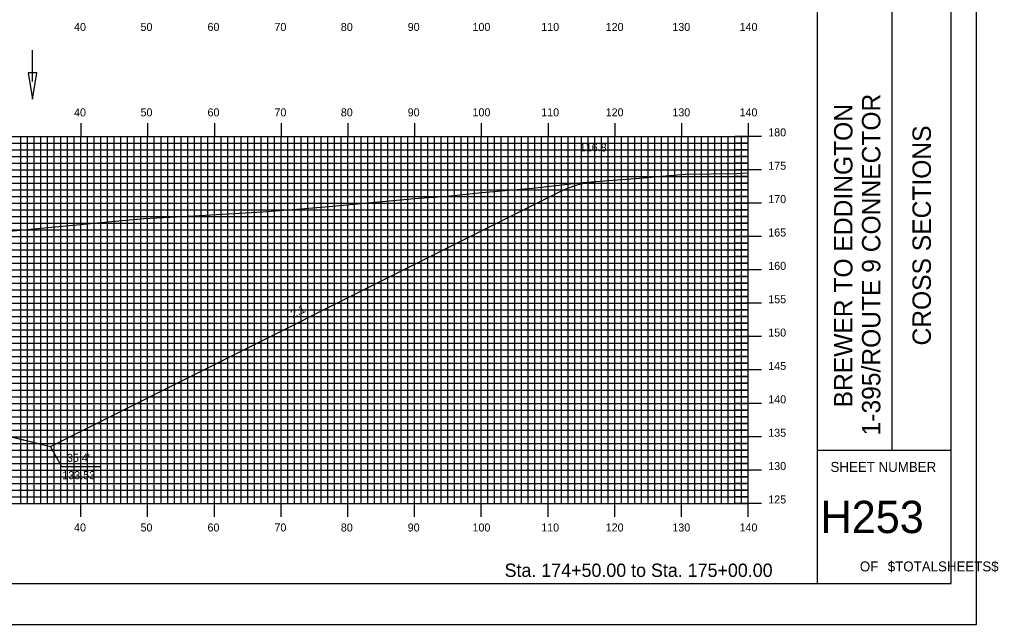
# Model space of a CAD drawing. Extents: x 1783828 to 1784171, y 442591 to 442811.
# Drawn here: x 1784024.3 to 1784171, y 442590.5 to 442681.2 of the extents above; entities that cross this region are included whole.
import ezdxf

# ---------------------------------------------------------------- set-up
doc = ezdxf.new("R2010")
doc.units = 0
for name, color, linetype in [('ANNOTATION', 7, 'Continuous'), ('BORDER', 7, 'Continuous'), ('D_Drainage_Ditch_Line', 7, 'Continuous'), ('D_Roadway_Centerline', 7, 'Continuous'), ('D_Roadway_SlopeLines', 7, 'Continuous'), ('D_Text_Standard', 7, 'Continuous'), ('H_V ANNOTATION', 7, 'Continuous'), ('MAJOR', 7, 'Continuous'), ('MINOR', 7, 'Continuous'), ('PLOT BOUNDARY', 7, 'Continuous'), ('S_Roadway_Centerline', 7, 'Continuous')]:
    doc.layers.add(name, color=color, linetype=linetype)

msp = doc.modelspace()

# ---------------------------------------------------------------- linework, layer by layer
at = {"layer": 'ANNOTATION'}
msp.add_lwpolyline([(1784036.34, 442614.18), (1784030.65, 442614.18), (1784028.93, 442617.2)], dxfattribs=at)
at = {"layer": 'BORDER'}
for p, q in [((1784143.89, 442596.67), (1784143.89, 442806.67)), ((1784155.07, 442616.67), (1784155.07, 442686.67)), ((1784155.07, 442616.67), (1784155.07, 442686.67)), ((1784143.89, 442616.67), (1784163.89, 442616.67)), ((1784143.89, 442616.67), (1784163.89, 442616.67))]:
    msp.add_line(p, q, dxfattribs=at)
msp.add_lwpolyline([(1783843.89, 442596.67), (1784163.89, 442596.67), (1784163.89, 442806.67), (1783843.89, 442806.67)], close=True, dxfattribs=at)
at = {"layer": 'D_Drainage_Ditch_Line'}
msp.add_line((1784026.24, 442671.87), (1784026.24, 442676.57), dxfattribs=at)
msp.add_lwpolyline([(1784026.89, 442673.18), (1784025.58, 442673.18), (1784026.24, 442669.24)], close=True, dxfattribs=at)
at = {"layer": 'D_Roadway_Centerline'}
msp.add_lwpolyline([(1783909.48, 442640.49), (1783910.73, 442640.48), (1783911.98, 442640.3), (1783913.23, 442639.94), (1783914.48, 442639.4), (1783959.31, 442616.98), (1783963.31, 442617.98), (1783973.49, 442620.53), (1783981.49, 442620.85), (1783993.49, 442621.11), (1784005.49, 442621.38), (1784013.49, 442621.06), (1784023.66, 442618.51), (1784028.93, 442617.2), (1784105.33, 442655.4), (1784106.58, 442655.96), (1784107.83, 442656.39), (1784109.08, 442656.7), (1784110.33, 442656.87)], dxfattribs=at)
at = {"layer": 'D_Roadway_SlopeLines'}
for points in [[(1784028.93, 442617.2), (1784105.33, 442655.4), (1784106.58, 442655.96), (1784107.83, 442656.39), (1784109.08, 442656.7), (1784110.33, 442656.87)], [(1784013.49, 442621.06), (1784028.93, 442617.2)]]:
    msp.add_lwpolyline(points, dxfattribs=at)
at = {"layer": 'MAJOR'}
for p, q in [((1784033.49, 442665.67), (1784033.49, 442663.67)), ((1784043.49, 442665.67), (1784043.49, 442663.67)), ((1784053.49, 442665.67), (1784053.49, 442663.67)), ((1784063.49, 442665.67), (1784063.49, 442663.67)), ((1784073.49, 442665.67), (1784073.49, 442663.67)), ((1784083.49, 442665.67), (1784083.49, 442663.67)), ((1784093.49, 442665.67), (1784093.49, 442663.67)), ((1784103.49, 442665.67), (1784103.49, 442663.67)), ((1784113.49, 442665.67), (1784113.49, 442663.67)), ((1784123.49, 442665.67), (1784123.49, 442663.67)), ((1784133.49, 442665.67), (1784133.49, 442663.67)), ((1783853.49, 442663.67), (1784133.49, 442663.67)), ((1783853.49, 442663.67), (1784133.49, 442663.67)), ((1784033.49, 442608.67), (1784033.49, 442663.67)), ((1784043.49, 442608.67), (1784043.49, 442663.67)), ((1784053.49, 442608.67), (1784053.49, 442663.67)), ((1784063.49, 442608.67), (1784063.49, 442663.67)), ((1784073.49, 442608.67), (1784073.49, 442663.67)), ((1784083.49, 442608.67), (1784083.49, 442663.67)), ((1784093.49, 442608.67), (1784093.49, 442663.67)), ((1784103.49, 442608.67), (1784103.49, 442663.67)), ((1784113.49, 442608.67), (1784113.49, 442663.67)), ((1784123.49, 442608.67), (1784123.49, 442663.67)), ((1784135.49, 442663.67), (1784131.48, 442663.67)), ((1784133.49, 442608.67), (1784133.49, 442663.67)), ((1784133.49, 442608.67), (1784133.49, 442663.67)), ((1783853.49, 442658.67), (1784133.49, 442658.67)), ((1784135.49, 442658.67), (1784131.48, 442658.67)), ((1783853.49, 442653.67), (1784133.49, 442653.67)), ((1784135.49, 442653.67), (1784131.48, 442653.67)), ((1783853.49, 442648.67), (1784133.49, 442648.67)), ((1784135.49, 442648.67), (1784131.48, 442648.67)), ((1783853.49, 442643.67), (1784133.49, 442643.67)), ((1784135.49, 442643.67), (1784131.48, 442643.67)), ((1783853.49, 442638.67), (1784133.49, 442638.67)), ((1784135.49, 442638.67), (1784131.48, 442638.67)), ((1783853.49, 442633.67), (1784133.49, 442633.67)), ((1784135.49, 442633.67), (1784131.48, 442633.67)), ((1783853.49, 442628.67), (1784133.49, 442628.67)), ((1784135.49, 442628.67), (1784131.48, 442628.67)), ((1783853.49, 442623.67), (1784133.49, 442623.67)), ((1784135.49, 442623.67), (1784131.48, 442623.67)), ((1783853.49, 442618.67), (1784133.49, 442618.67)), ((1784135.49, 442618.67), (1784131.48, 442618.67)), ((1783853.49, 442613.67), (1784133.49, 442613.67)), ((1784135.49, 442613.67), (1784131.48, 442613.67)), ((1783853.49, 442608.67), (1784133.49, 442608.67)), ((1783853.49, 442608.67), (1784133.49, 442608.67)), ((1784033.49, 442606.66), (1784033.49, 442608.67)), ((1784043.49, 442606.66), (1784043.49, 442608.67)), ((1784053.49, 442606.66), (1784053.49, 442608.67)), ((1784063.49, 442606.66), (1784063.49, 442608.67)), ((1784073.49, 442606.66), (1784073.49, 442608.67)), ((1784083.49, 442606.66), (1784083.49, 442608.67)), ((1784093.49, 442606.66), (1784093.49, 442608.67)), ((1784103.49, 442606.66), (1784103.49, 442608.67)), ((1784113.49, 442606.66), (1784113.49, 442608.67)), ((1784123.49, 442606.66), (1784123.49, 442608.67)), ((1784135.49, 442608.67), (1784131.48, 442608.67)), ((1784133.49, 442606.66), (1784133.49, 442608.67))]:
    msp.add_line(p, q, dxfattribs=at)
at = {"layer": 'MINOR'}
for p, q in [((1783853.49, 442662.67), (1784133.49, 442662.67)), ((1784024.49, 442608.67), (1784024.49, 442663.67)), ((1784025.49, 442608.67), (1784025.49, 442663.67)), ((1784026.49, 442608.67), (1784026.49, 442663.67)), ((1784027.49, 442608.67), (1784027.49, 442663.67)), ((1784028.49, 442608.67), (1784028.49, 442663.67)), ((1784029.49, 442608.67), (1784029.49, 442663.67)), ((1784030.49, 442608.67), (1784030.49, 442663.67)), ((1784031.49, 442608.67), (1784031.49, 442663.67)), ((1784032.49, 442608.67), (1784032.49, 442663.67)), ((1784034.49, 442608.67), (1784034.49, 442663.67)), ((1784035.49, 442608.67), (1784035.49, 442663.67)), ((1784036.49, 442608.67), (1784036.49, 442663.67)), ((1784037.49, 442608.67), (1784037.49, 442663.67)), ((1784038.49, 442608.67), (1784038.49, 442663.67)), ((1784039.49, 442608.67), (1784039.49, 442663.67)), ((1784040.49, 442608.67), (1784040.49, 442663.67)), ((1784041.49, 442608.67), (1784041.49, 442663.67)), ((1784042.49, 442608.67), (1784042.49, 442663.67)), ((1784044.49, 442608.67), (1784044.49, 442663.67)), ((1784045.49, 442608.67), (1784045.49, 442663.67)), ((1784046.49, 442608.67), (1784046.49, 442663.67)), ((1784047.49, 442608.67), (1784047.49, 442663.67)), ((1784048.49, 442608.67), (1784048.49, 442663.67)), ((1784049.49, 442608.67), (1784049.49, 442663.67)), ((1784050.49, 442608.67), (1784050.49, 442663.67)), ((1784051.49, 442608.67), (1784051.49, 442663.67)), ((1784052.49, 442608.67), (1784052.49, 442663.67)), ((1784054.49, 442608.67), (1784054.49, 442663.67)), ((1784055.49, 442608.67), (1784055.49, 442663.67)), ((1784056.49, 442608.67), (1784056.49, 442663.67)), ((1784057.49, 442608.67), (1784057.49, 442663.67)), ((1784058.49, 442608.67), (1784058.49, 442663.67)), ((1784059.49, 442608.67), (1784059.49, 442663.67)), ((1784060.49, 442608.67), (1784060.49, 442663.67)), ((1784061.49, 442608.67), (1784061.49, 442663.67)), ((1784062.49, 442608.67), (1784062.49, 442663.67)), ((1784064.49, 442608.67), (1784064.49, 442663.67)), ((1784065.49, 442608.67), (1784065.49, 442663.67)), ((1784066.49, 442608.67), (1784066.49, 442663.67)), ((1784067.49, 442608.67), (1784067.49, 442663.67)), ((1784068.49, 442608.67), (1784068.49, 442663.67)), ((1784069.49, 442608.67), (1784069.49, 442663.67)), ((1784070.49, 442608.67), (1784070.49, 442663.67)), ((1784071.49, 442608.67), (1784071.49, 442663.67)), ((1784072.49, 442608.67), (1784072.49, 442663.67)), ((1784074.49, 442608.67), (1784074.49, 442663.67)), ((1784075.49, 442608.67), (1784075.49, 442663.67)), ((1784076.49, 442608.67), (1784076.49, 442663.67)), ((1784077.49, 442608.67), (1784077.49, 442663.67)), ((1784078.49, 442608.67), (1784078.49, 442663.67)), ((1784079.49, 442608.67), (1784079.49, 442663.67)), ((1784080.49, 442608.67), (1784080.49, 442663.67)), ((1784081.49, 442608.67), (1784081.49, 442663.67)), ((1784082.49, 442608.67), (1784082.49, 442663.67)), ((1784084.49, 442608.67), (1784084.49, 442663.67)), ((1784085.49, 442608.67), (1784085.49, 442663.67)), ((1784086.49, 442608.67), (1784086.49, 442663.67)), ((1784087.49, 442608.67), (1784087.49, 442663.67)), ((1784088.49, 442608.67), (1784088.49, 442663.67)), ((1784089.49, 442608.67), (1784089.49, 442663.67)), ((1784090.49, 442608.67), (1784090.49, 442663.67)), ((1784091.49, 442608.67), (1784091.49, 442663.67)), ((1784092.49, 442608.67), (1784092.49, 442663.67)), ((1784094.49, 442608.67), (1784094.49, 442663.67)), ((1784095.49, 442608.67), (1784095.49, 442663.67)), ((1784096.49, 442608.67), (1784096.49, 442663.67)), ((1784097.49, 442608.67), (1784097.49, 442663.67)), ((1784098.49, 442608.67), (1784098.49, 442663.67)), ((1784099.49, 442608.67), (1784099.49, 442663.67)), ((1784100.49, 442608.67), (1784100.49, 442663.67)), ((1784101.49, 442608.67), (1784101.49, 442663.67)), ((1784102.49, 442608.67), (1784102.49, 442663.67)), ((1784104.49, 442608.67), (1784104.49, 442663.67)), ((1784105.49, 442608.67), (1784105.49, 442663.67)), ((1784106.49, 442608.67), (1784106.49, 442663.67)), ((1784107.49, 442608.67), (1784107.49, 442663.67)), ((1784108.49, 442608.67), (1784108.49, 442663.67)), ((1784109.49, 442608.67), (1784109.49, 442663.67)), ((1784110.49, 442608.67), (1784110.49, 442663.67)), ((1784111.49, 442608.67), (1784111.49, 442663.67)), ((1784112.49, 442608.67), (1784112.49, 442663.67)), ((1784114.49, 442608.67), (1784114.49, 442663.67)), ((1784115.49, 442608.67), (1784115.49, 442663.67)), ((1784116.49, 442608.67), (1784116.49, 442663.67)), ((1784117.49, 442608.67), (1784117.49, 442663.67)), ((1784118.49, 442608.67), (1784118.49, 442663.67)), ((1784119.49, 442608.67), (1784119.49, 442663.67)), ((1784120.49, 442608.67), (1784120.49, 442663.67)), ((1784121.49, 442608.67), (1784121.49, 442663.67)), ((1784122.49, 442608.67), (1784122.49, 442663.67)), ((1784124.49, 442608.67), (1784124.49, 442663.67)), ((1784125.49, 442608.67), (1784125.49, 442663.67)), ((1784126.49, 442608.67), (1784126.49, 442663.67)), ((1784127.49, 442608.67), (1784127.49, 442663.67)), ((1784128.49, 442608.67), (1784128.49, 442663.67)), ((1784129.49, 442608.67), (1784129.49, 442663.67)), ((1784130.49, 442608.67), (1784130.49, 442663.67)), ((1784133.49, 442662.67), (1784131.48, 442662.67)), ((1784131.49, 442608.67), (1784131.49, 442663.67)), ((1784132.49, 442608.67), (1784132.49, 442663.67)), ((1783853.49, 442661.67), (1784133.49, 442661.67)), ((1784133.49, 442661.67), (1784131.48, 442661.67)), ((1783853.49, 442660.67), (1784133.49, 442660.67)), ((1783853.49, 442659.67), (1784133.49, 442659.67)), ((1784133.49, 442660.67), (1784131.48, 442660.67)), ((1784133.49, 442659.67), (1784131.48, 442659.67)), ((1783853.49, 442657.67), (1784133.49, 442657.67)), ((1784133.49, 442657.67), (1784131.48, 442657.67)), ((1783853.49, 442656.67), (1784133.49, 442656.67)), ((1783853.49, 442655.67), (1784133.49, 442655.67)), ((1784133.49, 442656.67), (1784131.48, 442656.67)), ((1784133.49, 442655.67), (1784131.48, 442655.67)), ((1783853.49, 442654.67), (1784133.49, 442654.67)), ((1784133.49, 442654.67), (1784131.48, 442654.67)), ((1783853.49, 442652.67), (1784133.49, 442652.67)), ((1784133.49, 442652.67), (1784131.48, 442652.67)), ((1783853.49, 442651.67), (1784133.49, 442651.67)), ((1784133.49, 442651.67), (1784131.48, 442651.67)), ((1783853.49, 442650.67), (1784133.49, 442650.67)), ((1783853.49, 442649.67), (1784133.49, 442649.67)), ((1784133.49, 442650.67), (1784131.48, 442650.67)), ((1784133.49, 442649.67), (1784131.48, 442649.67)), ((1783853.49, 442647.67), (1784133.49, 442647.67)), ((1783853.49, 442646.67), (1784133.49, 442646.67)), ((1784133.49, 442647.67), (1784131.48, 442647.67)), ((1784133.49, 442646.67), (1784131.48, 442646.67)), ((1783853.49, 442645.67), (1784133.49, 442645.67)), ((1784133.49, 442645.67), (1784131.48, 442645.67)), ((1783853.49, 442644.67), (1784133.49, 442644.67)), ((1784133.49, 442644.67), (1784131.48, 442644.67)), ((1783853.49, 442642.67), (1784133.49, 442642.67)), ((1784133.49, 442642.67), (1784131.48, 442642.67)), ((1783853.49, 442641.67), (1784133.49, 442641.67)), ((1783853.49, 442640.67), (1784133.49, 442640.67)), ((1784133.49, 442641.67), (1784131.48, 442641.67)), ((1784133.49, 442640.67), (1784131.48, 442640.67)), ((1783853.49, 442639.67), (1784133.49, 442639.67)), ((1784133.49, 442639.67), (1784131.48, 442639.67)), ((1783853.49, 442637.67), (1784133.49, 442637.67)), ((1784133.49, 442637.67), (1784131.48, 442637.67)), ((1783853.49, 442636.67), (1784133.49, 442636.67)), ((1784133.49, 442636.67), (1784131.48, 442636.67)), ((1783853.49, 442635.67), (1784133.49, 442635.67)), ((1784133.49, 442635.67), (1784131.48, 442635.67)), ((1783853.49, 442634.67), (1784133.49, 442634.67)), ((1784133.49, 442634.67), (1784131.48, 442634.67)), ((1783853.49, 442632.67), (1784133.49, 442632.67)), ((1784133.49, 442632.67), (1784131.48, 442632.67)), ((1783853.49, 442631.67), (1784133.49, 442631.67)), ((1783853.49, 442630.67), (1784133.49, 442630.67)), ((1784133.49, 442631.67), (1784131.48, 442631.67)), ((1784133.49, 442630.67), (1784131.48, 442630.67)), ((1783853.49, 442629.67), (1784133.49, 442629.67)), ((1784133.49, 442629.67), (1784131.48, 442629.67)), ((1783853.49, 442627.67), (1784133.49, 442627.67)), ((1784133.49, 442627.67), (1784131.48, 442627.67)), ((1783853.49, 442626.67), (1784133.49, 442626.67)), ((1784133.49, 442626.67), (1784131.48, 442626.67)), ((1783853.49, 442625.67), (1784133.49, 442625.67)), ((1783853.49, 442624.67), (1784133.49, 442624.67)), ((1784133.49, 442625.67), (1784131.48, 442625.67)), ((1784133.49, 442624.67), (1784131.48, 442624.67)), ((1783853.49, 442622.67), (1784133.49, 442622.67)), ((1783853.49, 442621.67), (1784133.49, 442621.67)), ((1784133.49, 442622.67), (1784131.48, 442622.67)), ((1784133.49, 442621.67), (1784131.48, 442621.67)), ((1783853.49, 442620.67), (1784133.49, 442620.67)), ((1784133.49, 442620.67), (1784131.48, 442620.67)), ((1783853.49, 442619.67), (1784133.49, 442619.67)), ((1784133.49, 442619.67), (1784131.48, 442619.67)), ((1783853.49, 442617.67), (1784133.49, 442617.67)), ((1784133.49, 442617.67), (1784131.48, 442617.67)), ((1783853.49, 442616.67), (1784133.49, 442616.67)), ((1783853.49, 442615.67), (1784133.49, 442615.67)), ((1784133.49, 442616.67), (1784131.48, 442616.67)), ((1784133.49, 442615.67), (1784131.48, 442615.67)), ((1783853.49, 442614.67), (1784133.49, 442614.67)), ((1784133.49, 442614.67), (1784131.48, 442614.67)), ((1783853.49, 442612.67), (1784133.49, 442612.67)), ((1783853.49, 442611.67), (1784133.49, 442611.67)), ((1784133.49, 442612.67), (1784131.48, 442612.67)), ((1784133.49, 442611.67), (1784131.48, 442611.67)), ((1783853.49, 442610.67), (1784133.49, 442610.67)), ((1784133.49, 442610.67), (1784131.48, 442610.67)), ((1783853.49, 442609.67), (1784133.49, 442609.67)), ((1784133.49, 442609.67), (1784131.48, 442609.67))]:
    msp.add_line(p, q, dxfattribs=at)
at = {"layer": 'PLOT BOUNDARY'}
msp.add_lwpolyline([(1783827.7, 442590.55), (1784167.7, 442590.55), (1784167.7, 442810.55), (1783827.7, 442810.55)], close=True, dxfattribs=at)
at = {"layer": 'S_Roadway_Centerline'}
msp.add_lwpolyline([(1784019.62, 442649.19), (1784025.41, 442649.73), (1784030.19, 442650.17), (1784036.53, 442650.77), (1784042.93, 442651.37), (1784047.79, 442651.63), (1784060.69, 442652.38), (1784065.83, 442652.75), (1784070.64, 442653.16), (1784083.47, 442654.36), (1784088.43, 442654.72), (1784093.59, 442655.27), (1784101.12, 442655.9), (1784108.66, 442656.74), (1784117.19, 442657.41), (1784124.04, 442658.02), (1784131.79, 442658.13), (1784133.49, 442658.21)], dxfattribs=at)

# ---------------------------------------------------------------- texts
at = {"layer": 'ANNOTATION'}
msp.add_text('2:1', height=1.2, rotation=26.5651, dxfattribs=at).set_placement((1784065.27, 442636.41))
for s, p in [("35.4'", (1784031.4, 442614.91)), ('133.53', (1784030.7, 442612.31))]:
    msp.add_text(s, height=1.2, dxfattribs=at).set_placement(p)
at = {"layer": 'BORDER'}
for s, p in [('1-395/ROUTE 9 CONNECTOR', (1784153.29, 442618.87)), ('BREWER TO EDDINGTON', (1784149.11, 442623.07)), ('CROSS SECTIONS', (1784160.86, 442632.34)), ('CROSS SECTIONS', (1784160.86, 442632.34))]:
    msp.add_text(s, height=2.7557, rotation=90, dxfattribs=at).set_placement(p)
for s, height, p in [('SHEET NUMBER', 1.4905, (1784145.82, 442613.4)), ('SHEET NUMBER', 1.4905, (1784145.82, 442613.4)), ('H253', 4.839, (1784144.33, 442604.23)), ('OF', 1.491, (1784150.22, 442598.49)), ('OF', 1.491, (1784150.22, 442598.49)), ('$TOTALSHEETS$', 1.4905, (1784154.4, 442598.49))]:
    msp.add_text(s, height=height, dxfattribs=at).set_placement(p)
at = {"layer": 'D_Text_Standard'}
msp.add_text("116.8'", height=1.2, dxfattribs=at).set_placement((1784108.25, 442661.41))
at = {"layer": 'H_V ANNOTATION'}
for s, height, p in [('40', 1.2, (1784032.46, 442679.47)), ('50', 1.2, (1784042.42, 442679.47)), ('60', 1.2, (1784052.46, 442679.47)), ('70', 1.2, (1784062.49, 442679.47)), ('80', 1.2, (1784072.44, 442679.47)), ('90', 1.2, (1784082.46, 442679.47)), ('100', 1.2, (1784092.17, 442679.47)), ('110', 1.2, (1784102.47, 442679.47)), ('120', 1.2, (1784112.13, 442679.47)), ('130', 1.2, (1784122.12, 442679.47)), ('140', 1.2, (1784132.19, 442679.47)), ('40', 1.2, (1784032.46, 442666.67)), ('50', 1.2, (1784042.42, 442666.67)), ('60', 1.2, (1784052.46, 442666.67)), ('70', 1.2, (1784062.49, 442666.67)), ('80', 1.2, (1784072.44, 442666.67)), ('90', 1.2, (1784082.46, 442666.67)), ('100', 1.2, (1784092.17, 442666.67)), ('110', 1.2, (1784102.47, 442666.67)), ('120', 1.2, (1784112.13, 442666.67)), ('130', 1.2, (1784122.12, 442666.67)), ('140', 1.2, (1784132.19, 442666.67)), ('180', 1.2, (1784136.49, 442663.67)), ('175', 1.2, (1784136.49, 442658.67)), ('170', 1.2, (1784136.49, 442653.67)), ('165', 1.2, (1784136.49, 442648.67)), ('160', 1.2, (1784136.49, 442643.67)), ('155', 1.2, (1784136.49, 442638.67)), ('150', 1.2, (1784136.49, 442633.67)), ('145', 1.2, (1784136.49, 442628.67)), ('140', 1.2, (1784136.49, 442623.67)), ('135', 1.2, (1784136.49, 442618.67)), ('130', 1.2, (1784136.49, 442613.67)), ('125', 1.2, (1784136.49, 442608.67)), ('40', 1.2, (1784032.46, 442604.47)), ('50', 1.2, (1784042.42, 442604.47)), ('60', 1.2, (1784052.46, 442604.47)), ('70', 1.2, (1784062.49, 442604.47)), ('80', 1.2, (1784072.44, 442604.47)), ('90', 1.2, (1784082.46, 442604.47)), ('100', 1.2, (1784092.17, 442604.47)), ('110', 1.2, (1784102.47, 442604.47)), ('120', 1.2, (1784112.13, 442604.47)), ('130', 1.2, (1784122.12, 442604.47)), ('140', 1.2, (1784132.19, 442604.47)), ('Sta. 174+50.00 to Sta. 175+00.00', 2.0004, (1784096.98, 442597.66))]:
    msp.add_text(s, height=height, dxfattribs=at).set_placement(p)

doc.saveas('drawing.dxf')
